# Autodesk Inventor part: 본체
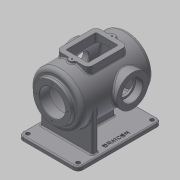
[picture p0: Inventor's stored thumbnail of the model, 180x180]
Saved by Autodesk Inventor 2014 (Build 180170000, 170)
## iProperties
Created: 2016-02
Part Number: 본체
Material: 일반
Document SubType Name: Modeling
Designer: mduedu
Density: 1 g/cm^3
Appearance: 기본값
Mass: 1432.37 g
Surface Area: 2614.18 cm^2
Volume: 1432.37 cm^3
Author: mduedu
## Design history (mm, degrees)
sketch "스케치2"
  geometry: L1 (0, 90)-(0, -90); L2 (65, -90)-(65, 90); L3 (65, 90)-(0, 90); L4 (65, -90)-(0, -90); 2 further points
  constraints: 8 end point, 2 horizontal, 1 coincident, 1 midpoint, 1 parallel, 1 vertical
  dimensions: "d3" = 180 distance of L1.start L1.end; "d5" = 130 diameter of L2 L1
revolve "회전1" sketch "스케치2" stored, may be unused: angle "d7" = 90 deg
sketch "스케치3"
  geometry: C1 r 47.5 at (0, 0); 1 further point
  constraints: 1 centre point, 1 coincident
  dimensions: "d8" = 95 diameter of C1
extrude "돌출2" join sketch "스케치3" distance "d10" = 10; taper "d11" = 0 deg
sketch "스케치5"
  geometry: L1 (47.5, 100)-(47.5, 90) reference; L2 (47.5, 90)-(65, 90) reference; L3 (65, 90)-(65, -90) reference; L4 (-65, -90)-(-65, 90) reference; L5 (-65, 90)-(-47.5, 90) reference; L6 (-47.5, 90)-(-47.5, 100) reference; L7 (-47.5, 100)-(47.5, 100) reference; L8 (55, 75)-(55, -75); L9 (0, 75)-(55, 75); L10 (0, 75)-(0, -75); L11 (65, -90)-(-65, -90) reference; L12 (55, -75)-(0, -75); 1 further point
  constraints: 9 end point, 2 parallel, 2 perpendicular, 1 midpoint, 1 vertical
  dimensions: "d13" = 10 distance between parallel lines of L3 L8; "d15" = 15 distance between parallel lines of L9 L2; "d203" = 15 distance between parallel lines of L11 L12
revolve "회전2" sketch "스케치5" stored, may be unused: angle "d16" = 90 deg
hole "구멍1" diameter "d19" = 65; stored, may be unused: countersink angle "d23" = 90 deg, drill point angle "d25" = 118 deg; dims "d17" = 10, "d18" = 10, "d20" = 6, "d21" = 4, "d22" = 2, "d24" = 8
node "작업 평면1"
sketch "스케치6"
  geometry: L1 (47.5, 100)-(-47.5, 100) reference; C1 r 40 at (0, -27); 1 further point
  constraints: 1 centre point, 1 vertical alignment
  dimensions: "d27" = 80 diameter of C1; "d29" = 127 distance from line of C1.centre L1
extrude "돌출3" join sketch "스케치6" stored distance "d30" = 10; taper "d31" = 0 deg
hole "구멍2" diameter "d34" = 42; stored, may be unused: countersink angle "d38" = 90 deg, drill point angle "d40" = 118 deg; dims "d32" = 10, "d33" = 10, "d35" = 6, "d36" = 52, "d37" = 18, "d39" = 8
sketch "스케치7" dims "d41" = 65
  geometry: C1 r 40 at (0, 0) reference; 3 further points
  constraints: 2 vertical alignment, 1 coincident, 2 other
hole "구멍3" sketch "스케치7" at (0, 32.5) diameter "d43" = 3.242; stored, may be unused: countersink angle "d47" = 90 deg, drill point angle "d49" = 118 deg; dims "d44" = 11, "d45" = 13, "d46" = 18, "d48" = 13
sketch "스케치8" dims "d53" = 80
  geometry: 3 further points
  constraints: 2 vertical alignment, 1 coincident, 2 other
hole "구멍4" sketch "스케치8" at (0, 40) diameter "d56" = 3.242; stored, may be unused: countersink angle "d60" = 90 deg, drill point angle "d62" = 118 deg; dims "d57" = 11, "d58" = 13, "d59" = 18, "d61" = 13
fillet "모깎기1" dims "d66" = 10
fillet "모깎기2" dims "d67" = 3
fillet "모깎기3" dims "d68" = 0.3
chamfer "모따기1" distance "d69" = 1; stored, may be unused: second distance "d70" = 2, angle "d71" = 45 deg
node "작업 평면5"
sketch "스케치10"
  geometry: L1 (-50, 0)-(50, 0); L2 (-65, 64)-(65, 64); L3 (65, 64)-(65, 50); L4 (65, 50)-(-65, 50); L5 (-65, 50)-(-65, 64); 3 further points
  constraints: 10 end point, 2 horizontal, 2 midpoint, 2 vertical, 1 coincident, 1 vertical alignment
  dimensions: "d132" = 100 distance of L1.start L1.end; "d158" = 50 distance between parallel lines of L4 L1; "d159" = 14 distance of L2.end L3.end; "d160" = 130 distance of L2.start L2.end
extrude "돌출5" join sketch "스케치10" stored distance "d84" = 10; taper "d85" = 0 deg
sketch "스케치11"
  geometry: L1 (-100, 64)-(-100, 50) reference; L2 (-100, 50)-(-100, -50); L3 (-65, 80)-(-65, -80) reference; L4 (-100, -50)-(-65, -50); L5 (-100, 50)-(0, 50) reference; 1 further point
  constraints: 4 end point, 1 collinear, 1 perpendicular, 1 point on line
  dimensions: "d161" = 100 distance between parallel lines of L4 L5
feature "리브1" sketch "스케치11" dims "d88" = 1, "d89" = 14, "d90" = 0, "d91" = 0, "d92" = 1, "d93" = 1
fillet "모깎기5" dims "d103" = 3
fillet "모깎기6" dims "d177" = 3
node "작업 평면6"
sketch "스케치15"
  geometry: L1 (-40, 50)-(40, 50); L2 (40, 50)-(40, -50); L3 (40, -50)-(-40, -50); L4 (-40, -50)-(-40, 50); C1 r 7.5 at (0, 50); C2 r 7.5 at (0, -50); 3 further points
  constraints: 8 end point, 2 centre point, 2 coincident, 2 midpoint, 2 parallel, 1 horizontal, 1 perpendicular, 1 vertical alignment
  dimensions: "d110" = 80 distance of L2.end L3.end; "d112" = 50 distance from line of L3 point (0, 0); "d113" = 100 distance of L1.end L2.end; "d149" = 40 distance from line of L4 point (0, 0); "d191" = 15 diameter of C1; "d192" = 15 diameter of C2
extrude "돌출8" join sketch "스케치15" stored distance "d114" = 10; taper "d115" = 0 deg
fillet "모깎기7" dims "d116" = 12, "d193" = 3
sketch "스케치16"
  geometry: L1 (-28, 50)-(-10.062, 50) reference; L2 (28, -50)-(10.062, -50) reference; L3 (40, 38)-(40, -38) reference; L4 (-40, -38)-(-40, 38) reference; L5 (-10.062, -50)-(-28, -50) reference; L6 (10.062, 50)-(28, 50) reference; L7 (-28, -38)-(28, -38); L8 (28, -38)-(28, 38); L9 (28, 38)-(-28, 38); L10 (-28, 38)-(-28, -38); L11 (-28, -38)-(28, 38); L12 (28, -38)-(-28, 38); A1 r 12 centre (28, 38) between (40, 38) and (28, 50) reference; A2 r 12 centre (28, -38) between (28, -50) and (40, -38) reference; A3 r 12 centre (-28, -38) between (-40, -38) and (-28, -50) reference; A4 r 12 centre (-28, 38) between (-28, 50) and (-40, 38) reference; A5 r 3 centre (10.062, -53) between (10.062, -50) and (7.187, -52.143) reference; A6 r 7.5 centre (0, -50) between (-7.187, -52.143) and (7.187, -52.143) reference; A7 r 3 centre (-10.062, -53) between (-7.187, -52.143) and (-10.062, -50) reference; A8 r 3 centre (-10.062, 53) between (-10.062, 50) and (-7.187, 52.143) reference; A9 r 7.5 centre (0, 50) between (7.187, 52.143) and (-7.187, 52.143) reference; A10 r 3 centre (10.062, 53) between (7.187, 52.143) and (10.062, 50) reference; 1 further point
  constraints: 12 end point, 2 midpoint, 2 parallel, 1 horizontal, 1 perpendicular
  dimensions: "d180" = 100 distance between parallel lines of L2 L1 (derived); "d181" = 80 distance between parallel lines of L3 L4 (derived); "d194" = 12 distance between parallel lines of L9 L6; "d195" = 12 distance between parallel lines of L3 L8
extrude "돌출9" cut sketch "스케치16" stored distance "d118" = 10; taper "d119" = 0 deg
fillet "모깎기15" dims "d183" = 3
fillet "모깎기8" dims "d120" = 3
sketch "스케치24"
  geometry: L1 (28, 35)-(28, -35) reference; L2 (25, -38)-(-25, -38) reference; L3 (-28, -35)-(-28, 35) reference; L4 (-25, 38)-(25, 38) reference; L5 (40, 38)-(40, -38) reference; L6 (10.062, 50)-(28, 50) reference; L7 (-28, 50)-(-10.062, 50) reference; L8 (-40, -38)-(-40, 38) reference; L9 (-10.062, -50)-(-28, -50) reference; L10 (28, -50)-(10.062, -50) reference; A1 r 3 centre (25, -35) between (25, -38) and (28, -35) reference; A2 r 3 centre (-25, -35) between (-28, -35) and (-25, -38) reference; A3 r 3 centre (-25, 35) between (-25, 38) and (-28, 35) reference; A4 r 3 centre (25, 35) between (28, 35) and (25, 38) reference; A5 r 12 centre (28, -38) between (28, -50) and (40, -38) reference; A6 r 12 centre (28, 38) between (40, 38) and (28, 50) reference; A7 r 3 centre (10.062, 53) between (7.187, 52.143) and (10.062, 50) reference; A8 r 7.5 centre (0, 50) between (7.187, 52.143) and (-7.187, 52.143) reference; A9 r 3 centre (-10.062, 53) between (-10.062, 50) and (-7.187, 52.143) reference; A10 r 12 centre (-28, 38) between (-28, 50) and (-40, 38) reference; A11 r 12 centre (-28, -38) between (-40, -38) and (-28, -50) reference; A12 r 3 centre (-10.062, -53) between (-7.187, -52.143) and (-10.062, -50) reference; A13 r 7.5 centre (0, -50) between (-7.187, -52.143) and (7.187, -52.143) reference; A14 r 3 centre (10.062, -53) between (10.062, -50) and (7.187, -52.143) reference; 3 further points
  constraints: 2 coincident
hole "구멍7" sketch "스케치24" at (0, 50), (0, -50) diameter "d196" = 3.242; stored, may be unused: countersink angle "d200" = 90 deg, drill point angle "d202" = 118 deg; dims "d197" = 9, "d198" = 4, "d199" = 2, "d201" = 11
sketch "스케치20"
  geometry: L1 (-75, 110)-(75, 110); L2 (75, 110)-(75, -100); L3 (75, -100)-(-75, -100); L4 (-75, -100)-(-75, 110); 2 further points
  constraints: 8 end point, 2 parallel, 1 horizontal, 1 midpoint, 1 perpendicular, 1 vertical alignment
  dimensions: "d162" = 150 distance of L1.start L1.end; "d164" = 210 distance of L1.end L2.end; "d165" = 110 distance from line of L1 point (0, 0)
extrude "돌출12" join sketch "스케치20" distance "d166" = 10; taper "d167" = 0 deg
fillet "모깎기12" dims "d168" = 12
fillet "모깎기13" dims "d169" = 3
fillet "모깎기14" dims "d170" = 3
sketch "스케치21"
  geometry: C1 r 5 at (-63, -98); C2 r 5 at (63, -98); C3 r 5 at (63, 88); C4 r 5 at (-63, 88); A1 r 12 centre (-63, -98) between (-75, -98) and (-63, -110) reference; A2 r 12 centre (-63, 88) between (-63, 100) and (-75, 88) reference; A3 r 12 centre (63, 88) between (75, 88) and (63, 100) reference; A4 r 12 centre (63, -98) between (63, -110) and (75, -98) reference; 1 further point
  constraints: 4 centre point, 4 coincident, 3 equal radius
  dimensions: "d171" = 10 diameter of C1
extrude "돌출13" cut sketch "스케치21" stored distance "d172" = 10; taper "d173" = 0 deg
sketch "스케치22"
  geometry: L1 (75, -98)-(75, 88) reference; 2 further points
  constraints: 1 horizontal alignment, 1 other
  dimensions: "d174" = 15 distance from line of L1 point (60, 0)
feature "엠보싱2" sketch "스케치22" dims "d3" = 180, "d5" = 130, "d16" = 90 deg, "d175" = 0.5, "d176" = 0
node "솔리드2"
pattern_circular "원형 패턴1" dims angle "d51" = 360 deg
mirror "대칭1"
pattern_circular "원형 패턴2" dims angle "d64" = 360 deg
node "투영된 루프3"
node "절단 모서리 투영1"
node "절단 모서리 투영2"
other parameters: "d26" = 75
